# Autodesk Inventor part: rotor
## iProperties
Shininess: 64.0
Length Units: 11269
Angle Units: 11279
Time Units: 11290
Mass Units: 11283
Length Display Precision: 3
Angle Display Precision: 2
Compacted: True
Part Number: rotor
Document SubType Name: Modeling
Created: 2004-05
Material: Par défaut
Designer: David
Density: 0.0
Volumn: 0.0
Area: 0.0
PropertySet Name: Model Information
Control State: 0
Master: False
Checked Out: False
Author: David
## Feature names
1. Révolution1 [Revolution]
2. Chanfrein1 [Chamfer]
